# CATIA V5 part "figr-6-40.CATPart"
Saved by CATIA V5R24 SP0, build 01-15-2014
Part number: Part1
Bounding box of the stored display mesh (mm): x 0 to 45, y 0 to 76.536, z 0 to 111.001
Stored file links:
  D:\KAVITA\CATIA V5-6R2014 Project_ Kavita\CATIA V5-6R2014_partfiles\Partfiles\c06_catia_v5-6r2014_prt\figr-6-40.CATPart
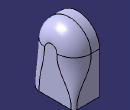
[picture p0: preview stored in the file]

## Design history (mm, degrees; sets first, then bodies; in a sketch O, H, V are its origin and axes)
Body1 (main body)
  Sketch1 on yz-plane, origin (0, 0, 0), H (0, 1, 0), V (0, 0, 1)
    line L1 (0, 0) -> (76.5361, 0)
    line L2 (76.5361, 0) -> (76.5361, 72.7325)
    line L3 (0, 0) -> (0, 72.7325)
    arc A1 centre (38.2681, 72.7325) radius 38.2681 from (76.5361, 72.7325) to (0, 72.7325) ccw
    horizontal: L1 H
    vertical: L2 V, L3 V
    tangency: A1 L3, A1 L2
  Pad1: profile Sketch1, direction (1, 0, 0), length 45
  Fillet1: on edge [face of Pad1 | face of Pad1] (x3)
